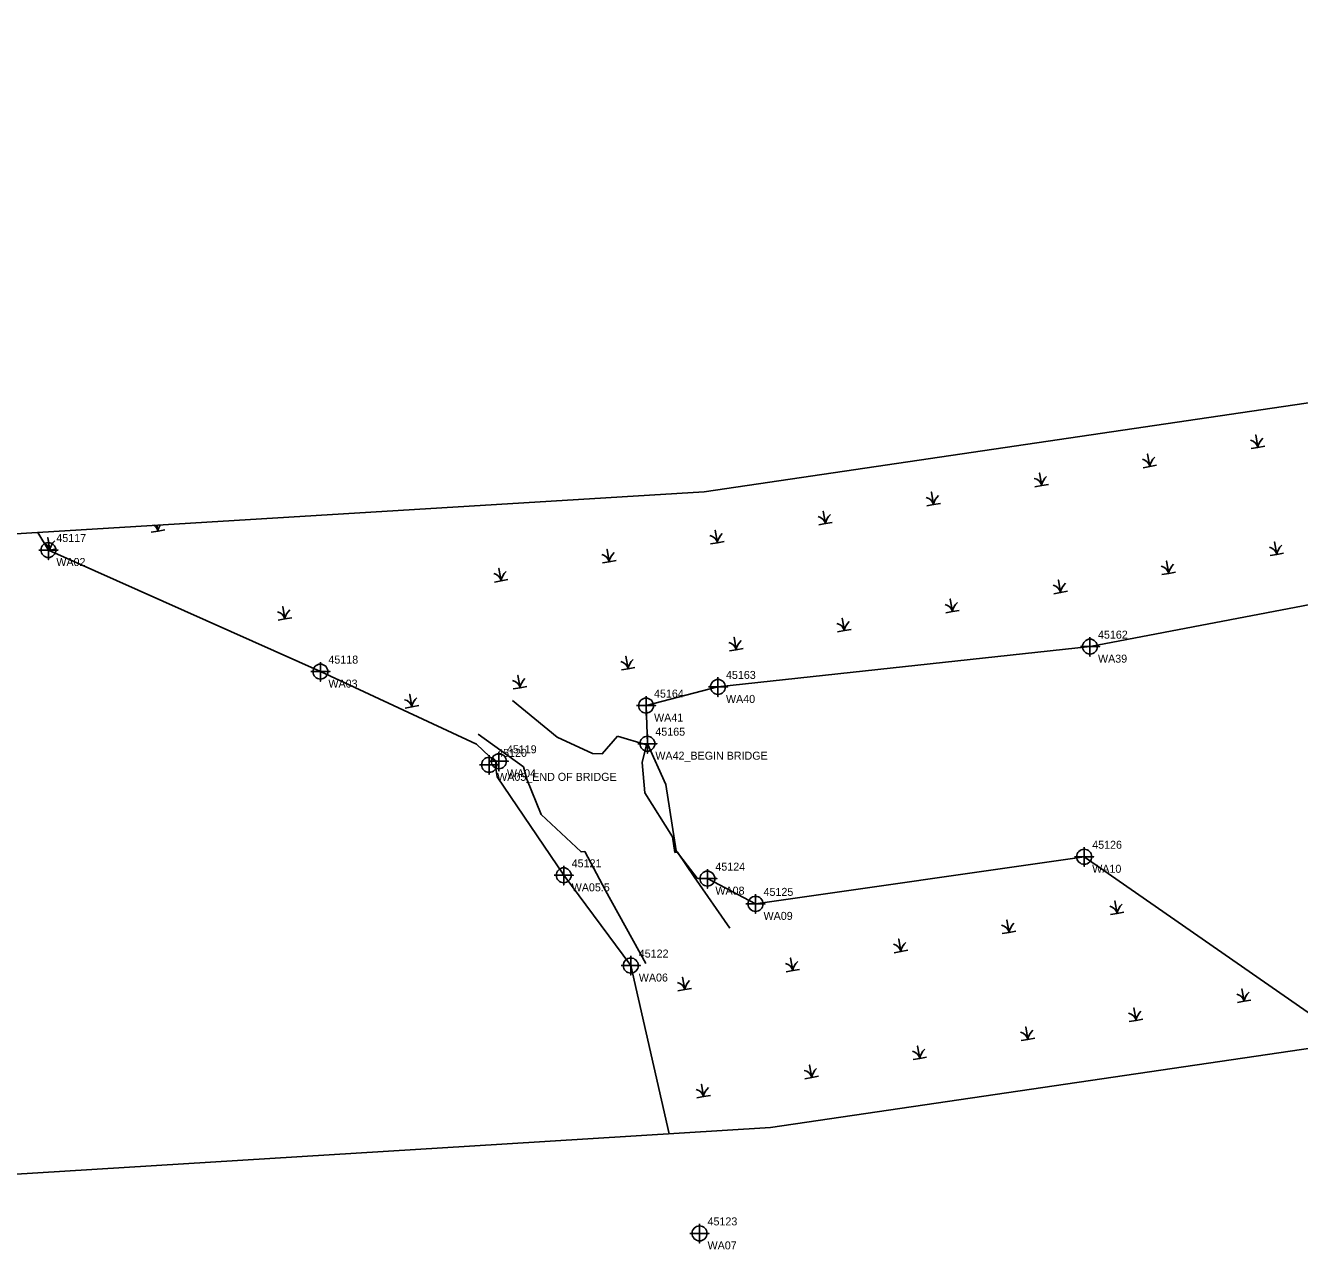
# Model space of a CAD drawing. Extents: x 2111078 to 2112839, y 581517 to 581907.
# Drawn here: x 2111367.6 to 2111765.7, y 581516.6 to 581899.2 of the extents above; entities that cross this region are included whole.
import ezdxf

# ---------------------------------------------------------------- set-up
doc = ezdxf.new("R2010")
doc.units = 0
for name, color, linetype in [('Default', 7, 'Continuous'), ('Exist Environmental Wetland Boundary', 7, 'Continuous'), ('Exist Environmental Wetland Boundary Cogo Comment', 7, 'Continuous'), ('Exist Environmental Wetland Boundary Cogo Number', 7, 'Continuous'), ('Exist Environmental Wetland Boundary Cogo Point CELL', 7, 'Continuous'), ('Exist Hydro Jurisdictional Stream or Body of Water Mitigable', 7, 'Continuous'), ('Exist Hydro Swamp or Marsh', 7, 'Continuous')]:
    doc.layers.add(name, color=color, linetype=linetype)

msp = doc.modelspace()

# ---------------------------------------------------------------- linework, layer by layer
at = {"layer": 'Default'}
msp.add_lwpolyline([(2111089.87, 581523.16), (2111077.52, 581722.78), (2111579.66, 581753.48), (2112568.99, 581899.18), (2112598.13, 581701.32), (2111600.4, 581554.74), (2111516.52, 581549.55)], close=True, dxfattribs=at)
at = {"layer": 'Exist Environmental Wetland Boundary'}
for points in [[(2112052.09, 581738.85), (2112043.26, 581752.76), (2111928.23, 581738.62), (2111810.46, 581726.15), (2111700.26, 581705.05), (2111584.01, 581692.46), (2111561.53, 581686.62), (2111561.94, 581674.72), (2111567.72, 581661.99), (2111570.98, 581641.26), (2111577.49, 581632.74), (2111580.7, 581632.54), (2111595.75, 581624.66), (2111698.44, 581639.38), (2111781.79, 581581.39)], [(2111568.75, 581552.78), (2111568.75, 581552.78), (2111556.76, 581605.38), (2111535.8, 581633.58), (2111514.99, 581664.32), (2111514.47, 581667.71), (2111514.55, 581668.87), (2111508.56, 581674.59), (2111459.78, 581697.25), (2111374.77, 581735.25), (2111371.48, 581740.75)]]:
    msp.add_lwpolyline(points, dxfattribs=at)
at = {"layer": 'Exist Environmental Wetland Boundary Cogo Point CELL'}
for points in [[(2111374.77, 581738.25), (2111374.77, 581732.25), (2111374.77, 581735.25), (2111377.77, 581735.25), (2111371.77, 581735.25)], [(2111700.25, 581708.05), (2111700.25, 581702.05), (2111700.25, 581705.05), (2111703.25, 581705.05), (2111697.25, 581705.05)], [(2111459.78, 581700.25), (2111459.78, 581694.25), (2111459.78, 581697.25), (2111462.78, 581697.25), (2111456.78, 581697.25)], [(2111584.01, 581695.46), (2111584.01, 581689.46), (2111584.01, 581692.46), (2111587.01, 581692.46), (2111581.01, 581692.46)], [(2111561.53, 581689.62), (2111561.53, 581683.62), (2111561.53, 581686.62), (2111564.53, 581686.62), (2111558.53, 581686.62)], [(2111561.94, 581677.72), (2111561.94, 581671.72), (2111561.94, 581674.72), (2111564.94, 581674.72), (2111558.94, 581674.72)], [(2111515.55, 581672.22), (2111515.55, 581666.22), (2111515.55, 581669.22), (2111518.55, 581669.22), (2111512.55, 581669.22)], [(2111512.51, 581671.11), (2111512.51, 581665.11), (2111512.51, 581668.11), (2111515.51, 581668.11), (2111509.51, 581668.11)], [(2111698.44, 581642.38), (2111698.44, 581636.38), (2111698.44, 581639.38), (2111701.44, 581639.38), (2111695.44, 581639.38)], [(2111535.8, 581636.58), (2111535.8, 581630.58), (2111535.8, 581633.58), (2111538.8, 581633.58), (2111532.8, 581633.58)], [(2111580.7, 581635.54), (2111580.7, 581629.54), (2111580.7, 581632.54), (2111583.7, 581632.54), (2111577.7, 581632.54)], [(2111595.75, 581627.66), (2111595.75, 581621.66), (2111595.75, 581624.66), (2111598.75, 581624.66), (2111592.75, 581624.66)], [(2111556.76, 581608.38), (2111556.76, 581602.38), (2111556.76, 581605.38), (2111559.76, 581605.38), (2111553.76, 581605.38)], [(2111578.25, 581524.67), (2111578.25, 581518.67), (2111578.25, 581521.67), (2111581.25, 581521.67), (2111575.25, 581521.67)]]:
    msp.add_lwpolyline(points, dxfattribs=at)
for centre in [(2111374.77, 581735.25), (2111700.25, 581705.05), (2111459.78, 581697.25), (2111584.01, 581692.46), (2111561.53, 581686.62), (2111561.94, 581674.72), (2111512.51, 581668.11), (2111515.55, 581669.22), (2111698.44, 581639.38), (2111535.8, 581633.58), (2111580.7, 581632.54), (2111595.75, 581624.66), (2111556.76, 581605.38), (2111578.25, 581521.67)]:
    msp.add_circle(centre, 2.34, dxfattribs=at)
at = {"layer": 'Exist Hydro Jurisdictional Stream or Body of Water Mitigable'}
msp.add_line((2111552.63, 581677.08), (2111561.67, 581674.38), dxfattribs=at)
for points in [[(2111552.63, 581677.08), (2111547.85, 581671.56), (2111544.75, 581671.66), (2111533.81, 581676.81), (2111519.85, 581688.2)], [(2111561.47, 581606.07), (2111548.91, 581628.8), (2111542.37, 581640.99), (2111541.25, 581640.91), (2111528.72, 581652.62), (2111524.26, 581663.63), (2111523.22, 581667.47), (2111509.12, 581677.74)], [(2111587.68, 581617.11), (2111576.59, 581633.07), (2111571.39, 581640.81), (2111570.54, 581640.75), (2111569.77, 581645.65), (2111561.11, 581659.37), (2111560.3, 581668.81), (2111561.67, 581674.38)]]:
    msp.add_lwpolyline(points, dxfattribs=at)
at = {"layer": 'Exist Hydro Swamp or Marsh'}
for points in [[(2111750.61, 581766.94), (2111752.73, 581767.31), (2111752.04, 581771.2), (2111752.73, 581767.31), (2111754.85, 581767.69)], [(2111716.83, 581760.98), (2111718.95, 581761.36), (2111718.26, 581765.24), (2111718.95, 581761.36), (2111721.07, 581761.73)], [(2111683.05, 581755.03), (2111685.17, 581755.4), (2111684.48, 581759.29), (2111685.17, 581755.4), (2111687.29, 581755.77)], [(2111649.27, 581749.07), (2111651.39, 581749.44), (2111650.7, 581753.33), (2111651.39, 581749.44), (2111653.51, 581749.82)], [(2111615.49, 581743.11), (2111617.61, 581743.49), (2111616.92, 581747.37), (2111617.61, 581743.49), (2111619.73, 581743.86)], [(2111406.92, 581740.81), (2111409.04, 581741.18), (2111408.71, 581743.03)], [(2111408.71, 581743.03), (2111409.04, 581741.18), (2111411.15, 581741.55)], [(2111581.71, 581737.16), (2111583.83, 581737.53), (2111583.14, 581741.42), (2111583.83, 581737.53), (2111585.95, 581737.9)], [(2111374.96, 581735.17), (2111375.26, 581735.22), (2111374.57, 581739.11), (2111375.26, 581735.22), (2111377.37, 581735.6)], [(2111756.5, 581733.51), (2111758.62, 581733.88), (2111757.94, 581737.77), (2111758.62, 581733.88), (2111760.74, 581734.26)], [(2111547.93, 581731.2), (2111550.05, 581731.57), (2111549.36, 581735.46), (2111550.05, 581731.57), (2111552.17, 581731.95)], [(2111722.72, 581727.55), (2111724.84, 581727.93), (2111724.16, 581731.81), (2111724.84, 581727.93), (2111726.96, 581728.3)], [(2111514.15, 581725.25), (2111516.27, 581725.62), (2111515.58, 581729.5), (2111516.27, 581725.62), (2111518.39, 581725.99)], [(2111688.94, 581721.6), (2111691.06, 581721.97), (2111690.38, 581725.86), (2111691.06, 581721.97), (2111693.18, 581722.34)], [(2111655.16, 581715.64), (2111657.28, 581716.01), (2111656.6, 581719.9), (2111657.28, 581716.01), (2111659.4, 581716.39)], [(2111446.59, 581713.33), (2111448.71, 581713.71), (2111448.02, 581717.59), (2111448.71, 581713.71), (2111450.83, 581714.08)], [(2111621.39, 581709.68), (2111623.5, 581710.06), (2111622.82, 581713.94), (2111623.5, 581710.06), (2111625.62, 581710.43)], [(2111587.61, 581703.73), (2111589.72, 581704.1), (2111589.04, 581707.99), (2111589.72, 581704.1), (2111591.84, 581704.48)], [(2111553.83, 581697.77), (2111555.94, 581698.15), (2111555.26, 581702.03), (2111555.94, 581698.15), (2111558.06, 581698.52)], [(2111520.05, 581691.82), (2111522.16, 581692.19), (2111521.48, 581696.07), (2111522.16, 581692.19), (2111524.28, 581692.56)], [(2111486.27, 581685.86), (2111488.38, 581686.23), (2111487.7, 581690.12), (2111488.38, 581686.23), (2111490.5, 581686.61)], [(2111706.63, 581621.31), (2111708.75, 581621.68), (2111708.06, 581625.57), (2111708.75, 581621.68), (2111710.86, 581622.06)], [(2111672.85, 581615.35), (2111674.97, 581615.73), (2111674.28, 581619.61), (2111674.97, 581615.73), (2111677.08, 581616.1)], [(2111639.07, 581609.4), (2111641.19, 581609.77), (2111640.5, 581613.65), (2111641.19, 581609.77), (2111643.3, 581610.14)], [(2111605.29, 581603.44), (2111607.41, 581603.81), (2111606.72, 581607.7), (2111607.41, 581603.81), (2111609.52, 581604.19)], [(2111571.51, 581597.48), (2111573.63, 581597.86), (2111572.94, 581601.74), (2111573.63, 581597.86), (2111575.74, 581598.23)], [(2111746.3, 581593.84), (2111748.42, 581594.21), (2111747.74, 581598.09), (2111748.42, 581594.21), (2111750.54, 581594.58)], [(2111712.52, 581587.88), (2111714.64, 581588.25), (2111713.96, 581592.14), (2111714.64, 581588.25), (2111716.76, 581588.63)], [(2111678.74, 581581.92), (2111680.86, 581582.3), (2111680.18, 581586.18), (2111680.86, 581582.3), (2111682.98, 581582.67)], [(2111644.96, 581575.97), (2111647.08, 581576.34), (2111646.4, 581580.23), (2111647.08, 581576.34), (2111649.2, 581576.71)], [(2111611.18, 581570.01), (2111613.3, 581570.38), (2111612.62, 581574.27), (2111613.3, 581570.38), (2111615.42, 581570.76)], [(2111577.4, 581564.05), (2111579.52, 581564.43), (2111578.84, 581568.31), (2111579.52, 581564.43), (2111581.64, 581564.8)]]:
    msp.add_lwpolyline(points, dxfattribs=at)
for centre, radius, start, end in [((2111749.75, 581766.56), 3.07, 14.1403, 77.535), ((2111757.48, 581766.61), 4.81, 132.1274, 171.6222), ((2111715.97, 581760.61), 3.07, 14.1403, 77.535), ((2111723.7, 581760.66), 4.81, 132.1274, 171.6222), ((2111682.19, 581754.65), 3.07, 14.1403, 77.535), ((2111689.92, 581754.7), 4.81, 132.1274, 171.6222), ((2111648.41, 581748.69), 3.07, 14.1403, 77.535), ((2111656.14, 581748.74), 4.81, 132.1274, 171.6222), ((2111614.63, 581742.74), 3.07, 14.1403, 77.535), ((2111622.36, 581742.79), 4.81, 132.1274, 171.6222), ((2111406.05, 581740.43), 3.07, 14.1403, 55.8167), ((2111413.79, 581740.48), 4.81, 147.0578, 171.6222), ((2111580.85, 581736.78), 3.07, 14.1403, 77.535), ((2111588.58, 581736.83), 4.81, 132.1274, 171.6222), ((2111372.27, 581734.47), 3.07, 14.1403, 65.0361), ((2111380.01, 581734.52), 4.81, 132.1274, 171.6222), ((2111755.64, 581733.13), 3.07, 14.1403, 77.535), ((2111763.38, 581733.18), 4.81, 132.1274, 171.6222), ((2111547.07, 581730.82), 3.07, 14.1403, 77.535), ((2111554.8, 581730.87), 4.81, 132.1274, 171.6222), ((2111513.29, 581724.87), 3.07, 14.1403, 77.535), ((2111521.02, 581724.92), 4.81, 132.1274, 171.6222), ((2111721.86, 581727.18), 3.07, 14.1403, 77.535), ((2111729.6, 581727.23), 4.81, 132.1274, 171.6222), ((2111688.08, 581721.22), 3.07, 14.1403, 77.535), ((2111695.82, 581721.27), 4.81, 132.1274, 171.6222), ((2111445.73, 581712.96), 3.07, 14.1403, 77.535), ((2111453.46, 581713.01), 4.81, 132.1274, 171.6222), ((2111654.3, 581715.26), 3.07, 14.1403, 77.535), ((2111662.04, 581715.31), 4.81, 132.1274, 171.6222), ((2111620.52, 581709.31), 3.07, 14.1403, 77.535), ((2111628.26, 581709.36), 4.81, 132.1274, 171.6222), ((2111586.74, 581703.35), 3.07, 14.1403, 77.535), ((2111594.48, 581703.4), 4.81, 132.1274, 171.6222), ((2111552.96, 581697.39), 3.07, 14.1403, 77.535), ((2111560.7, 581697.45), 4.81, 132.1274, 171.6222), ((2111519.18, 581691.44), 3.07, 14.1403, 77.535), ((2111526.92, 581691.49), 4.81, 132.1274, 171.6222), ((2111485.4, 581685.48), 3.07, 14.1403, 77.535), ((2111493.14, 581685.53), 4.81, 132.1274, 171.6222), ((2111713.5, 581620.98), 4.81, 132.1274, 171.6222), ((2111705.76, 581620.93), 3.07, 14.1403, 77.535), ((2111671.98, 581614.97), 3.07, 14.1403, 77.535), ((2111679.72, 581615.03), 4.81, 132.1274, 171.6222), ((2111645.94, 581609.07), 4.81, 132.1274, 171.6222), ((2111638.21, 581609.02), 3.07, 14.1403, 77.535), ((2111604.43, 581603.06), 3.07, 14.1403, 77.535), ((2111612.16, 581603.11), 4.81, 132.1274, 171.6222), ((2111578.38, 581597.16), 4.81, 132.1274, 171.6222), ((2111570.65, 581597.11), 3.07, 14.1403, 77.535), ((2111745.44, 581593.46), 3.07, 14.1403, 77.535), ((2111753.17, 581593.51), 4.81, 132.1274, 171.6222), ((2111711.66, 581587.5), 3.07, 14.1403, 77.535), ((2111719.39, 581587.55), 4.81, 132.1274, 171.6222), ((2111677.88, 581581.55), 3.07, 14.1403, 77.535), ((2111685.62, 581581.6), 4.81, 132.1274, 171.6222), ((2111644.1, 581575.59), 3.07, 14.1403, 77.535), ((2111651.84, 581575.64), 4.81, 132.1274, 171.6222), ((2111610.32, 581569.63), 3.07, 14.1403, 77.535), ((2111618.06, 581569.68), 4.81, 132.1274, 171.6222), ((2111576.54, 581563.68), 3.07, 14.1403, 77.535), ((2111584.28, 581563.73), 4.81, 132.1274, 171.6222)]:
    msp.add_arc(centre, radius, start, end, dxfattribs=at)

# ---------------------------------------------------------------- texts
at = {"layer": 'Exist Environmental Wetland Boundary Cogo Comment'}
for s, p in [('WA02', (2111377.27, 581730.25)), ('WA39', (2111702.75, 581700.05)), ('WA03', (2111462.28, 581692.25)), ('WA40', (2111586.51, 581687.46)), ('WA41', (2111564.03, 581681.62)), ('WA42_BEGIN BRIDGE', (2111564.44, 581669.72)), ('WA05_END OF BRIDGE', (2111515.01, 581663.11)), ('WA04', (2111518.05, 581664.22)), ('WA10', (2111700.94, 581634.38)), ('WA05.5', (2111538.3, 581628.58)), ('WA08', (2111583.2, 581627.54)), ('WA09', (2111598.25, 581619.66)), ('WA06', (2111559.26, 581600.38)), ('WA07', (2111580.75, 581516.67))]:
    msp.add_text(s, height=2.5, dxfattribs=at).set_placement(p)
at = {"layer": 'Exist Environmental Wetland Boundary Cogo Number'}
for s, p in [('45117', (2111377.27, 581737.75)), ('45162', (2111702.75, 581707.55)), ('45118', (2111462.28, 581699.75)), ('45163', (2111586.51, 581694.96)), ('45164', (2111564.03, 581689.12)), ('45165', (2111564.44, 581677.22)), ('45120', (2111515.01, 581670.61)), ('45119', (2111518.05, 581671.72)), ('45126', (2111700.94, 581641.88)), ('45121', (2111538.3, 581636.08)), ('45124', (2111583.2, 581635.04)), ('45125', (2111598.25, 581627.16)), ('45122', (2111559.26, 581607.88)), ('45123', (2111580.75, 581524.17))]:
    msp.add_text(s, height=2.5, dxfattribs=at).set_placement(p)

doc.saveas('drawing.dxf')
